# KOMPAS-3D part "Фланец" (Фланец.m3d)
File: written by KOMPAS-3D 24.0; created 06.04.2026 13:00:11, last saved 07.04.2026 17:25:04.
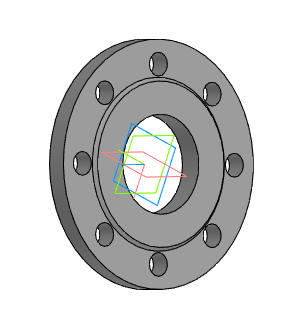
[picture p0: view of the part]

Document properties: Автор: R2D2; Полное имя файла: E:\Работа\Зайцев\Солянка\VSR1-13V-PED-F Клапан запорно-регулирующий DN.ru\DN80\исходные материалы\Фланец.m3d

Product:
- Component [standard]: (unnamed)  | qty 1  | Материал: ВЧ40 ГОСТ 7293-85 (density 7200 kg/m3); Масса: 3.71; additional columns: 80-16-01-2-B-ВЧ40-II-dв 90,5; Фланец; ГОСТ 33259-2015
- Part/product: Фланец
    Масса: 3.445383

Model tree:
1. Эскиз:8
2. Элемент выдавливания:8
     Расстояние 2 = 20
3. Эскиз:10  (with: Грань.Элемент выдавливания:8, Ребро.Элемент выдавливания:8)
4. Элемент выдавливания:12
5. Массив по концентрической сетке:1  (with: Элемент выдавливания:12, Эскиз:10)  (8 pattern instances)
     Шаг 2 = 360

Expressions: v520+50
Referenced files in C:\Program Files\ASCON\KOMPAS-3D v24\Libs\PolynomLib\DATA\vault\Methods\Kompas\3D\: PLib_Flange_GOST_33259_1401.m3d
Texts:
  BOSimple***Material:38d6725a-5efe-48e1-b177-a7817acb862a
  BOSimple***PART:ea516cba-f3a9-eea2-8abd-faaa5dc4bf65***SHORTLOC:B6A6_23E38AE8DB154823[II;2;Круглый;80;16;90,5;0;ВЧ40 ГОСТ 7293-85]
  Ch34
  Плоскость XY.Начало координат
  Ось Z.Начало координат
  Plane ZX. Origin
  Плоскость ZX.Начало координат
